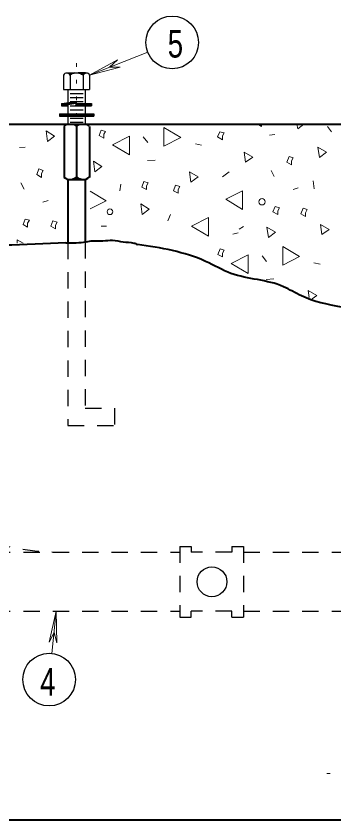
# Model space of a CAD drawing. Extents: x 312583 to 312854, y 144419 to 144597.
# Drawn here: x 312747.96 to 312756.71, y 144438.03 to 144460.18 of the extents above; entities that cross this region are included whole.
import ezdxf

# ---------------------------------------------------------------- set-up
doc = ezdxf.new("R2010")
doc.units = 0
doc.header["$LTSCALE"] = 0.3
doc.linetypes.add('DOTTED', pattern=[1.5, 0.3, -1.2])
doc.linetypes.add('SHORT_DASHED', pattern=[2.7, 1.5, -1.2])
doc.layers.add('1', color=7, linetype='Continuous', lineweight=25)
doc.layers.add('2', color=7, linetype='Continuous', lineweight=13)

msp = doc.modelspace()

# ---------------------------------------------------------------- linework, layer by layer
at = {"layer": '1', "linetype": 'DOTTED', "lineweight": 13}
msp.add_line((312749.6233, 144458.8804), (312749.6233, 144457.2014), dxfattribs=at)
at = {"layer": '1'}
for p, q in [((312749.263, 144458.5507), (312749.263, 144458.1597)), ((312749.355, 144458.612), (312749.8916, 144458.612)), ((312749.447, 144458.5507), (312749.447, 144458.1597)), ((312749.8073, 144458.5507), (312749.8073, 144458.1597)), ((312749.9836, 144458.5507), (312749.9836, 144458.1597)), ((312749.263, 144458.1597), (312749.9836, 144458.1597)), ((312749.3856, 144458.1597), (312749.3856, 144457.2014)), ((312749.447, 144458.0447), (312749.8073, 144458.0447)), ((312749.861, 144458.1597), (312749.861, 144457.2014)), ((312749.447, 144457.9374), (312749.8073, 144457.9374)), ((312749.447, 144457.8224), (312749.8073, 144457.8224)), ((312749.2093, 144457.7687), (312749.2093, 144457.7074)), ((312749.447, 144457.7074), (312749.8073, 144457.7074)), ((312749.447, 144457.5924), (312749.8073, 144457.5924)), ((312749.5926, 144457.7074), (312750.0373, 144457.7074)), ((312749.608, 144457.7687), (312750.0373, 144457.7687)), ((312750.0373, 144457.7687), (312750.0373, 144457.7074)), ((312749.1556, 144457.485), (312750.0986, 144457.485)), ((312749.1556, 144457.485), (312749.1556, 144457.4237)), ((312749.1556, 144457.4697), (312750.0986, 144457.4697)), ((312749.1556, 144457.4544), (312750.0986, 144457.4544)), ((312749.1556, 144457.439), (312750.0986, 144457.439)), ((312749.1556, 144457.4237), (312750.0986, 144457.4237)), ((312749.447, 144457.37), (312749.8073, 144457.37)), ((312750.0986, 144457.485), (312750.0986, 144457.4237)), ((312749.3856, 144457.2014), (312749.861, 144457.2014)), ((312749.447, 144457.255), (312749.8073, 144457.255)), ((312749.447, 144457.2014), (312749.7996, 144457.2014))]:
    msp.add_line(p, q, dxfattribs=at)
at = {"layer": '1', "lineweight": 40}
for p, q in [((312734.5276, 144457.2014), (312777.9746, 144457.2014)), ((312749.6233, 144457.2014), (312749.6233, 144455.6757)), ((312749.2783, 144457.14), (312749.2783, 144455.737)), ((312749.976, 144457.14), (312749.976, 144455.737)), ((312749.3856, 144455.6757), (312749.3856, 144453.9354)), ((312749.447, 144455.6757), (312749.7996, 144455.6757)), ((312749.861, 144455.6757), (312749.861, 144453.9584)), ((312733.8913, 144438.0347), (312778.611, 144438.0347))]:
    msp.add_line(p, q, dxfattribs=at)
at = {"layer": '1', "linetype": 'SHORT_DASHED'}
for p, q in [((312749.3856, 144453.9354), (312749.3856, 144448.8984)), ((312749.861, 144453.9507), (312749.861, 144449.3737)), ((312749.3856, 144448.8984), (312750.666, 144448.8984)), ((312752.4676, 144445.571), (312752.4676, 144443.6237)), ((312752.4676, 144445.571), (312752.782, 144445.571)), ((312752.782, 144445.571), (312752.782, 144445.41)), ((312753.9013, 144445.571), (312753.9013, 144445.41)), ((312753.9013, 144445.571), (312754.2233, 144445.571)), ((312754.2233, 144445.571), (312754.2233, 144443.6237)), ((312745.7286, 144445.41), (312752.4676, 144445.41)), ((312753.9013, 144445.41), (312752.782, 144445.41)), ((312754.2233, 144445.41), (312763.9676, 144445.41)), ((312745.7286, 144443.7847), (312752.4676, 144443.7847)), ((312752.782, 144443.6237), (312752.782, 144443.7847)), ((312753.9013, 144443.7847), (312752.782, 144443.7847)), ((312753.9013, 144443.6237), (312753.9013, 144443.7847)), ((312754.2233, 144443.7847), (312763.9676, 144443.7847)), ((312752.4676, 144443.6237), (312752.782, 144443.6237)), ((312753.9013, 144443.6237), (312754.2233, 144443.6237))]:
    msp.add_line(p, q, dxfattribs=at)
at = {"layer": '1'}
for points in [[(312749.378, 144458.612), (312749.5773, 144458.612), (312749.5466, 144458.6044), (312749.5236, 144458.5967), (312749.4853, 144458.5814), (312749.447, 144458.5584), (312749.4316, 144458.5814), (312749.4163, 144458.589), (312749.3856, 144458.6044), (312749.562, 144458.6044), (312749.516, 144458.5967), (312749.4776, 144458.5814), (312749.447, 144458.566), (312749.4163, 144458.589), (312749.401, 144458.6044), (312749.539, 144458.6044), (312749.493, 144458.589), (312749.447, 144458.566), (312749.4086, 144458.6044), (312749.5236, 144458.6044), (312749.447, 144458.5737), (312749.4163, 144458.5967), (312749.516, 144458.6044), (312749.447, 144458.5737), (312749.424, 144458.5967), (312749.5006, 144458.5967), (312749.447, 144458.5814), (312749.4316, 144458.5967), (312749.4776, 144458.5967), (312749.447, 144458.5814), (312749.4393, 144458.5967), (312749.4623, 144458.589), (312749.447, 144458.589)], [(312749.8686, 144458.612), (312749.6693, 144458.612), (312749.7076, 144458.6044), (312749.7306, 144458.5967), (312749.7613, 144458.5814), (312749.7996, 144458.5584), (312749.815, 144458.5814), (312749.8303, 144458.589), (312749.861, 144458.6044), (312749.6846, 144458.6044), (312749.7383, 144458.5967), (312749.7766, 144458.5814), (312749.7996, 144458.566), (312749.8303, 144458.589), (312749.8533, 144458.6044), (312749.7076, 144458.6044), (312749.7613, 144458.589), (312749.7996, 144458.566), (312749.838, 144458.6044), (312749.723, 144458.6044), (312749.7996, 144458.5737), (312749.8303, 144458.5967), (312749.7383, 144458.6044), (312749.8073, 144458.5737), (312749.8226, 144458.5967), (312749.7536, 144458.5967), (312749.7996, 144458.5814), (312749.815, 144458.5967), (312749.769, 144458.5967), (312749.7996, 144458.5814), (312749.8073, 144458.5967), (312749.7843, 144458.589), (312749.7996, 144458.589)], [(312749.2093, 144457.7687), (312749.6233, 144457.8224), (312749.5926, 144457.7074)], [(312749.3856, 144457.7074), (312749.217, 144457.715), (312749.217, 144457.761), (312749.6156, 144457.8147), (312749.6003, 144457.7687), (312749.3856, 144457.738), (312749.378, 144457.715), (312749.217, 144457.7227), (312749.2246, 144457.7534), (312749.608, 144457.807), (312749.5926, 144457.7764), (312749.3703, 144457.738), (312749.3703, 144457.7227), (312749.2246, 144457.7304), (312749.2246, 144457.7457), (312749.585, 144457.7994), (312749.5926, 144457.784), (312749.378, 144457.7457), (312749.3626, 144457.738), (312749.3166, 144457.7304), (312749.2323, 144457.738), (312749.5773, 144457.7917), (312749.2936, 144457.738)], [(312749.608, 144457.7687), (312749.2093, 144457.7074), (312749.3856, 144457.7074)], [(312749.6003, 144457.715), (312750.0296, 144457.715), (312750.0296, 144457.761), (312749.6156, 144457.7534), (312749.6003, 144457.7227), (312750.022, 144457.7227), (312750.022, 144457.7534), (312749.6233, 144457.7457), (312749.608, 144457.7304), (312750.0143, 144457.7304), (312750.0066, 144457.738), (312750.0066, 144457.7457), (312749.6233, 144457.7457), (312749.6156, 144457.738), (312750.0066, 144457.738)], [(312749.5006, 144457.2014), (312749.7536, 144457.2014), (312749.723, 144457.1937), (312749.7, 144457.186), (312749.6693, 144457.1707), (312749.654, 144457.163), (312749.631, 144457.1477), (312749.6233, 144457.14), (312749.5773, 144457.1707), (312749.5313, 144457.1937), (312749.5083, 144457.1937), (312749.7383, 144457.2014), (312749.7153, 144457.1937), (312749.7, 144457.1937), (312749.6693, 144457.1784), (312749.6386, 144457.163), (312749.631, 144457.1554), (312749.6233, 144457.1477), (312749.585, 144457.1784), (312749.5313, 144457.1937), (312749.7, 144457.1937), (312749.6616, 144457.1784), (312749.6233, 144457.1554), (312749.5543, 144457.1937), (312749.6846, 144457.1937), (312749.6233, 144457.1554), (312749.562, 144457.186), (312749.677, 144457.1937), (312749.631, 144457.163), (312749.585, 144457.186), (312749.654, 144457.186), (312749.6233, 144457.1784), (312749.585, 144457.1784), (312749.608, 144457.1707), (312749.6156, 144457.186), (312749.6233, 144457.163), (312749.6386, 144457.1784), (312749.6463, 144457.1784), (312749.6616, 144457.186)]]:
    msp.add_lwpolyline(points, dxfattribs=at)
at = {"layer": '1', "lineweight": 40}
msp.add_lwpolyline([(312749.5006, 144455.6757), (312749.7536, 144455.6757), (312749.723, 144455.6834), (312749.7, 144455.691), (312749.6693, 144455.6987), (312749.654, 144455.714), (312749.631, 144455.7294), (312749.6233, 144455.7294), (312749.5773, 144455.6987), (312749.5313, 144455.6834), (312749.5083, 144455.6757), (312749.7383, 144455.6757), (312749.7153, 144455.6834), (312749.7, 144455.6834), (312749.6693, 144455.691), (312749.6386, 144455.7064), (312749.631, 144455.7217), (312749.6233, 144455.7294), (312749.585, 144455.6987), (312749.5313, 144455.6834), (312749.7, 144455.6834), (312749.6616, 144455.691), (312749.6233, 144455.7217), (312749.5543, 144455.6834), (312749.6846, 144455.6834), (312749.6233, 144455.7217), (312749.562, 144455.6834), (312749.677, 144455.6834), (312749.631, 144455.714), (312749.585, 144455.691), (312749.654, 144455.691), (312749.6233, 144455.6987), (312749.585, 144455.691), (312749.608, 144455.7064), (312749.6156, 144455.691), (312749.6233, 144455.714), (312749.6386, 144455.6987), (312749.6463, 144455.6987), (312749.6616, 144455.691)], dxfattribs=at)
at = {"layer": '1', "linetype": 'SHORT_DASHED'}
msp.add_lwpolyline([(312749.861, 144449.3737), (312750.666, 144449.3737), (312750.666, 144448.8984)], dxfattribs=at)
at = {"layer": '1'}
msp.add_circle((312753.3544, 144444.5955), 0.4108, dxfattribs=at)
for centre, radius, start, end in [((312749.3559, 144458.5118), 0.0993, 25.60064, 154.39936), ((312749.6246, 144458.2985), 0.3126, 55.04559, 124.95441), ((312749.8932, 144458.5118), 0.0993, 25.60064, 154.39936), ((312749.4498, 144456.9293), 0.272, 50.00693, 129.99306), ((312749.7993, 144456.9293), 0.272, 50.00694, 129.99307)]:
    msp.add_arc(centre, radius, start, end, dxfattribs=at)
at = {"layer": '1', "lineweight": 40}
for centre, start, end in [((312749.4498, 144455.9466), 230.00694, 309.99307), ((312749.7993, 144455.9466), 230.00693, 309.99306)]:
    msp.add_arc(centre, 0.272, start, end, dxfattribs=at)
at = {"layer": '1', "linetype": 'SHORT_DASHED'}
msp.add_arc((312749.0649, 144451.1639), 5.75, 180, 270, dxfattribs=at)
at = {"layer": '1', "lineweight": 40}
for points in [[(312749.332, 144453.9354), (312745.9203, 144453.7974), (312742.3246, 144453.8357), (312739.7256, 144454.2037), (312737.1726, 144454.6637), (312735.7696, 144455.691), (312735.5166, 144457.2167)], [(312749.332, 144453.9354), (312749.6156, 144453.9354), (312749.884, 144453.9584), (312750.0756, 144453.989), (312750.3516, 144453.989), (312750.6123, 144454.0044), (312750.9113, 144453.9584), (312751.2026, 144453.9277), (312751.3023, 144453.8894)], [(312756.922, 144452.1644), (312755.818, 144452.471), (312755.3273, 144452.724), (312753.8783, 144453.092), (312753.1806, 144453.4217), (312751.3023, 144453.8894)]]:
    msp.add_spline(points, degree=3, dxfattribs=at)
at = {"layer": '2'}
for p, q in [((312751.586, 144459.187), (312749.9836, 144458.5507)), ((312749.9836, 144458.5507), (312750.7503, 144458.9724)), ((312750.7503, 144458.9724), (312750.5356, 144458.773)), ((312749.9836, 144458.5507), (312750.827, 144458.773)), ((312750.827, 144458.773), (312750.5356, 144458.773)), ((312754.6143, 144457.2014), (312754.7216, 144457.14)), ((312754.7216, 144457.14), (312754.7216, 144457.2014)), ((312755.6953, 144457.2014), (312755.7183, 144457.071)), ((312755.7183, 144457.071), (312755.887, 144457.2014)), ((312756.5386, 144457.14), (312756.646, 144456.9944)), ((312751.4633, 144456.8487), (312751.586, 144456.6954)), ((312754.9363, 144456.9024), (312755.0896, 144456.9177)), ((312748.0516, 144456.5574), (312748.205, 144456.5727)), ((312752.897, 144456.657), (312753.0656, 144456.6187)), ((312751.5783, 144456.197), (312751.793, 144456.2124)), ((312753.8323, 144455.8904), (312753.6483, 144455.7524)), ((312754.9823, 144455.9287), (312755.0666, 144455.76)), ((312756.1476, 144455.6374), (312756.1706, 144455.4227)), ((312748.09, 144455.5837), (312748.182, 144455.415)), ((312750.8193, 144455.369), (312750.8423, 144455.553)), ((312755.588, 144455.3997), (312755.7336, 144455.4457)), ((312748.6956, 144455.0547), (312748.8413, 144455.1007)), ((312752.2146, 144454.7097), (312752.138, 144454.541)), ((312750.3056, 144454.3877), (312750.4513, 144454.3877)), ((312754.1006, 144454.311), (312754.2233, 144454.38)), ((312753.932, 144454.173), (312754.0776, 144454.2037)), ((312754.737, 144453.575), (312754.8596, 144453.4217)), ((312756.163, 144453.3834), (312756.3393, 144453.345)), ((312754.852, 144452.9234), (312755.059, 144452.9387)), ((312749.0636, 144443.7847), (312748.872, 144442.9337)), ((312748.941, 144442.6194), (312749.0636, 144443.7847)), ((312749.0636, 144443.7847), (312749.079, 144442.9107)), ((312748.872, 144442.9337), (312749.0023, 144443.1944)), ((312749.079, 144442.9107), (312749.0023, 144443.1944))]:
    msp.add_line(p, q, dxfattribs=at)
at = {"layer": '2', "linetype": 'DOTTED'}
msp.add_line((312757.9953, 144439.315), (312756.1783, 144439.315), dxfattribs=at)
at = {"layer": '2'}
for points in [[(312748.826, 144456.726), (312749.0176, 144456.8717), (312748.7876, 144457.0174)], [(312750.3746, 144456.9254), (312750.4206, 144457.002), (312750.3056, 144457.0404), (312750.2443, 144456.887), (312750.3746, 144456.818)], [(312752.0306, 144457.1094), (312752.0306, 144456.5957), (312752.4983, 144456.8334)], [(312753.6406, 144456.8794), (312753.6866, 144456.9637), (312753.5716, 144456.9944), (312753.5103, 144456.8487), (312753.6406, 144456.772)], [(312751.08, 144456.358), (312751.08, 144456.8717), (312750.6123, 144456.634)], [(312756.3163, 144456.2814), (312756.508, 144456.427), (312756.2703, 144456.565)], [(312754.277, 144456.151), (312754.4763, 144456.2967), (312754.2386, 144456.4347)], [(312755.5496, 144456.1894), (312755.5956, 144456.2737), (312755.4806, 144456.312), (312755.4193, 144456.1587), (312755.5496, 144456.082)], [(312750.1293, 144455.8904), (312750.321, 144456.036), (312750.091, 144456.1817)], [(312748.6573, 144455.8444), (312748.7033, 144455.9287), (312748.5883, 144455.967), (312748.527, 144455.8137), (312748.6573, 144455.737)], [(312752.7743, 144455.6067), (312752.9736, 144455.7524), (312752.736, 144455.8904)], [(312751.5476, 144455.4994), (312751.5936, 144455.5837), (312751.4786, 144455.622), (312751.425, 144455.4687), (312751.5476, 144455.3997)], [(312752.4216, 144455.3997), (312752.4676, 144455.484), (312752.3526, 144455.5224), (312752.2913, 144455.369), (312752.4216, 144455.3)], [(312754.2003, 144454.8554), (312754.2003, 144455.369), (312753.7326, 144455.1314)], [(312751.4326, 144454.7174), (312751.6243, 144454.863), (312751.3943, 144455.0087)], [(312755.1663, 144454.817), (312755.2123, 144454.9014), (312755.0973, 144454.932), (312755.036, 144454.7864), (312755.1663, 144454.7097)], [(312755.933, 144454.7634), (312755.979, 144454.8477), (312755.864, 144454.886), (312755.8026, 144454.7327), (312755.933, 144454.656)], [(312748.274, 144454.472), (312748.3276, 144454.5564), (312748.205, 144454.587), (312748.1513, 144454.4414), (312748.274, 144454.3647)], [(312749.0406, 144454.4184), (312749.0866, 144454.5027), (312748.9716, 144454.541), (312748.918, 144454.3877), (312749.0406, 144454.3187)], [(312753.2573, 144454.1194), (312753.2573, 144454.633), (312752.7896, 144454.3954)], [(312754.9133, 144454.081), (312755.105, 144454.2267), (312754.8673, 144454.3647)], [(312756.3853, 144454.1577), (312756.5846, 144454.3034), (312756.347, 144454.4414)], [(312755.3043, 144453.8357), (312755.3043, 144453.322), (312755.7643, 144453.5597)], [(312753.6483, 144453.6517), (312753.6943, 144453.7284), (312753.5793, 144453.7667), (312753.518, 144453.6134), (312753.6483, 144453.5444)], [(312754.3536, 144453.0844), (312754.3536, 144453.598), (312753.886, 144453.3604)]]:
    msp.add_lwpolyline(points, close=True, dxfattribs=at)
for points in [[(312749.999, 144454.8707), (312750.436, 144455.0854), (312749.999, 144455.3537)], [(312748.1513, 144453.92), (312747.9826, 144454.0197), (312747.9903, 144453.92)], [(312756.117, 144452.3867), (312756.2396, 144452.4787), (312756.0096, 144452.6167), (312756.0326, 144452.425)]]:
    msp.add_lwpolyline(points, dxfattribs=at)
at = {"layer": '2', "lineweight": 25}
for centre in [(312752.2587, 144459.4541), (312748.8681, 144441.9001)]:
    msp.add_circle(centre, 0.7254, dxfattribs=at)
at = {"layer": '2'}
for centre, radius in [((312754.7348, 144455.0631), 0.0865), ((312750.5447, 144454.7889), 0.0784)]:
    msp.add_circle(centre, radius, dxfattribs=at)

# ---------------------------------------------------------------- texts
at = {"layer": '2', "width": 0.75}
for s, p in [('5', (312752.1351, 144459.0369)), ('4', (312748.6207, 144441.4623))]:
    msp.add_text(s, height=0.76, dxfattribs=at).set_placement(p)

doc.saveas('drawing.dxf')
